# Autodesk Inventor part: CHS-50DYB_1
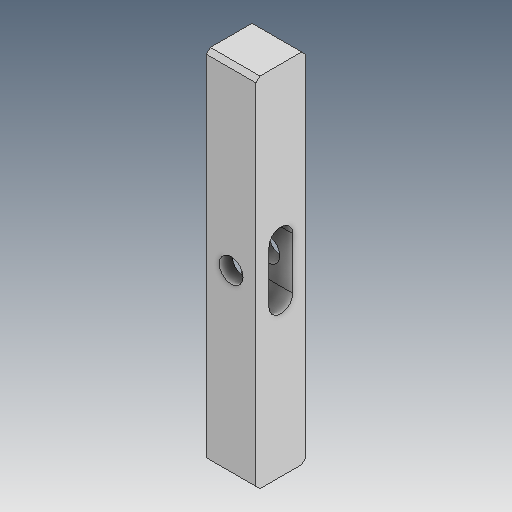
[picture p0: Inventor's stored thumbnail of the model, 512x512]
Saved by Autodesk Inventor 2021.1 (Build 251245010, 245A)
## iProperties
Created: 2019-04
Part Number: CHS-50DYB_1
Material: Ogólny
Document SubType Name: Modeling
Designer: user
Density: 1 g/cm^3
Appearance: Domyślna
Author: user
Revision Number: ÈÎºÎ
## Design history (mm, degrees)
feature "ÊäÈë1"
node "Bryła1"
